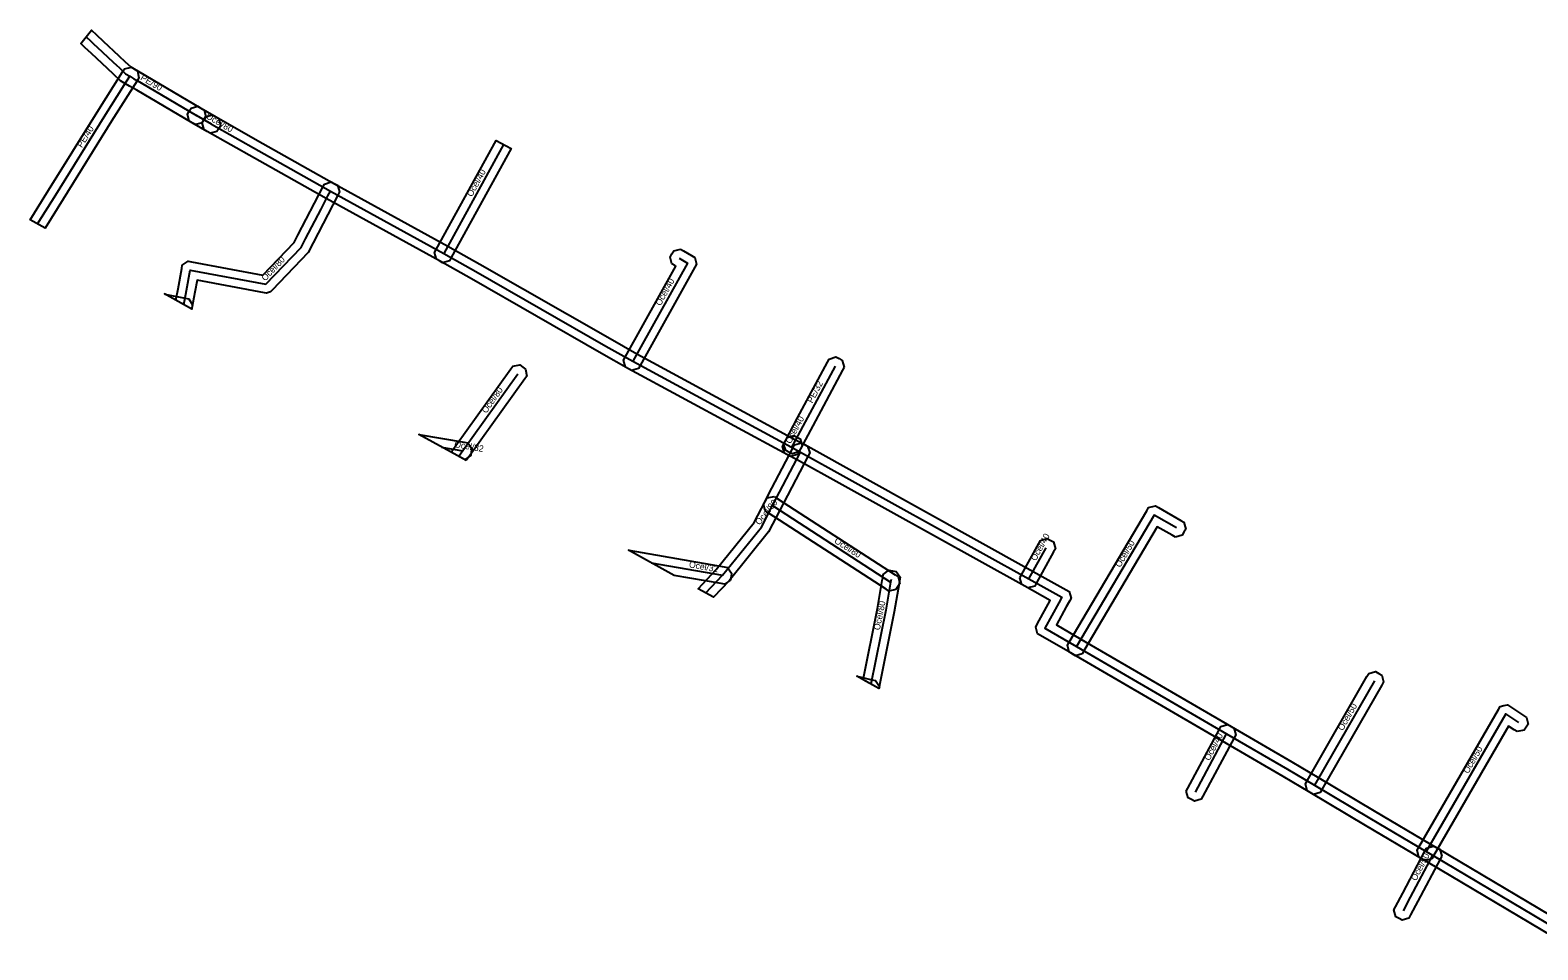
# Model space of a CAD drawing. Extents: x -749340 to -748632, y -965391 to -964902.
# Drawn here: x -749339.6 to -749163.1, y -965009.4 to -964901.7 of the extents above; entities that cross this region are included whole.
import ezdxf

# ---------------------------------------------------------------- set-up
doc = ezdxf.new("R2010")
doc.units = 0
for name, color, linetype in [('1', 7, 'Continuous'), ('14', 7, 'Continuous'), ('18', 7, 'Continuous'), ('20', 7, 'Continuous')]:
    doc.layers.add(name, color=color, linetype=linetype)

msp = doc.modelspace()

# ---------------------------------------------------------------- linework, layer by layer
at = {"layer": '1'}
for points in [[(-749333.19, -964903.71), (-749333.68, -964903.25), (-749332.42, -964901.69), (-749331.82, -964902.25), (-749331.06, -964902.97), (-749329.2, -964904.71), (-749328.47, -964905.4), (-749327.82, -964906), (-749327.43, -964906.23), (-749326.95, -964906.51), (-749326.11, -964907.01), (-749319.61, -964910.82), (-749319.25, -964911.03), (-749319.04, -964911.83), (-749319.25, -964912.19), (-749319.46, -964912.54), (-749320.26, -964912.75), (-749320.62, -964912.54), (-749327.12, -964908.73), (-749327.96, -964908.24), (-749328.44, -964907.96), (-749329.02, -964907.62), (-749329.83, -964906.85), (-749330.56, -964906.17), (-749332.42, -964904.43)], [(-749335.75, -964921.49), (-749337.85, -964924.86), (-749339.6, -964923.89), (-749337.45, -964920.43), (-749331.77, -964911.3), (-749328.78, -964906.56), (-749328.56, -964906.21), (-749327.75, -964906.03), (-749327.4, -964906.25), (-749327.05, -964906.47), (-749326.87, -964907.28), (-749327.09, -964907.63), (-749330.07, -964912.36)], [(-749318.54, -964913.76), (-749318.9, -964913.55), (-749320.62, -964912.54), (-749320.98, -964912.33), (-749321.19, -964911.53), (-749320.98, -964911.17), (-749320.77, -964910.82), (-749319.97, -964910.61), (-749319.61, -964910.82), (-749317.88, -964911.83), (-749317.53, -964912.04), (-749317.32, -964912.84), (-749317.53, -964913.2), (-749317.74, -964913.55)], [(-749292.07, -964927.36), (-749285.07, -964914.63), (-749283.29, -964915.56), (-749290.32, -964928.33), (-749290.52, -964928.69), (-749291.32, -964928.92), (-749291.68, -964928.72), (-749292.04, -964928.52), (-749292.27, -964927.73)], [(-749320.66, -964934.24), (-749320.68, -964934.35), (-749322.53, -964933.33), (-749322.29, -964932), (-749321.86, -964929.62), (-749321.79, -964929.21), (-749321.45, -964928.97), (-749321.11, -964928.73), (-749320.7, -964928.81), (-749312.35, -964930.37), (-749308.71, -964926.54), (-749308.26, -964925.68), (-749305.35, -964920.08), (-749305.16, -964919.71), (-749304.36, -964919.46), (-749304, -964919.66), (-749303.63, -964919.85), (-749303.38, -964920.64), (-749303.57, -964921.01), (-749306.49, -964926.6), (-749307.07, -964927.72), (-749311.27, -964932.14), (-749311.45, -964932.33), (-749311.93, -964932.48), (-749312.18, -964932.44), (-749320.07, -964930.96), (-749320.32, -964932.36)], [(-749263.48, -964927.33), (-749263.12, -964927.54), (-749262.18, -964928.09), (-749261.82, -964928.3), (-749261.61, -964929.09), (-749261.81, -964929.44), (-749268.21, -964940.95), (-749268.41, -964941.32), (-749269.21, -964941.54), (-749269.57, -964941.34), (-749269.93, -964941.14), (-749270.16, -964940.34), (-749269.96, -964939.98), (-749264.03, -964929.33), (-749264.13, -964929.27), (-749264.48, -964929.06), (-749264.7, -964928.26), (-749264.49, -964927.9), (-749264.28, -964927.55)], [(-749320.67, -964934.26), (-749320.68, -964934.35), (-749323.87, -964932.58), (-749323.82, -964932.59), (-749321.45, -964933.08), (-749321.04, -964933.17), (-749320.58, -964933.86)], [(-749288.56, -964952.1), (-749290.33, -964951.13), (-749289.77, -964950.35), (-749283.34, -964941.37), (-749283.1, -964941.04), (-749282.28, -964940.9), (-749281.95, -964941.14), (-749281.61, -964941.38), (-749281.47, -964942.2), (-749281.71, -964942.54), (-749288.15, -964951.52)], [(-749244.33, -964941.15), (-749244.52, -964941.51), (-749248.01, -964948.03), (-749249.45, -964950.71), (-749249.64, -964951.08), (-749250.43, -964951.32), (-749250.8, -964951.12), (-749251.16, -964950.93), (-749251.41, -964950.14), (-749251.21, -964949.77), (-749249.77, -964947.09), (-749246.29, -964940.57), (-749246.09, -964940.21), (-749245.3, -964939.96), (-749244.93, -964940.16), (-749244.57, -964940.36)], [(-749288.72, -964951.99), (-749288.78, -964951.98), (-749294.09, -964949.05), (-749288.79, -964949.95), (-749288.38, -964950.02), (-749287.9, -964950.7), (-749287.97, -964951.1), (-749288.04, -964951.51)], [(-749249.25, -964950.35), (-749249.45, -964950.71), (-749249.6, -964951), (-749249.8, -964951.37), (-749250.59, -964951.61), (-749250.95, -964951.41), (-749251.32, -964951.22), (-749251.56, -964950.43), (-749251.36, -964950.06), (-749251.21, -964949.77), (-749251.01, -964949.41), (-749250.22, -964949.17), (-749249.86, -964949.36), (-749249.49, -964949.56)], [(-749257.8, -964966.18), (-749259.62, -964968.1), (-749261.42, -964967.1), (-749259.31, -964964.86), (-749254.86, -964959.35), (-749253.59, -964956.91), (-749253.21, -964956.15), (-749250.32, -964950.64), (-749250.13, -964950.27), (-749249.34, -964950.02), (-749248.97, -964950.21), (-749248.6, -964950.41), (-749248.36, -964951.2), (-749248.55, -964951.56), (-749251.43, -964957.07), (-749251.81, -964957.82), (-749253.18, -964960.45)], [(-749252.51, -964956.3), (-749252.16, -964956.52), (-749238.34, -964965.48), (-749237.99, -964965.7), (-749237.82, -964966.51), (-749238.05, -964966.86), (-749238.27, -964967.21), (-749239.08, -964967.38), (-749239.43, -964967.15), (-749253.24, -964958.2), (-749253.59, -964957.98), (-749253.77, -964957.17), (-749253.54, -964956.82), (-749253.32, -964956.47)], [(-749205.56, -964961.06), (-749205.92, -964960.85), (-749207.68, -964959.84), (-749216.26, -964974.39), (-749216.47, -964974.75), (-749217.27, -964974.96), (-749217.63, -964974.75), (-749217.99, -964974.54), (-749218.19, -964973.73), (-749217.98, -964973.38), (-749208.91, -964957.97), (-749208.7, -964957.61), (-749207.9, -964957.4), (-749207.54, -964957.61), (-749204.93, -964959.12), (-749204.57, -964959.32), (-749204.35, -964960.12), (-749204.56, -964960.48), (-749204.76, -964960.84)], [(-749223.78, -964965.83), (-749223.58, -964965.46), (-749221.56, -964961.82), (-749221.36, -964961.45), (-749220.57, -964961.22), (-749220.2, -964961.42), (-749219.84, -964961.62), (-749219.61, -964962.42), (-749219.81, -964962.78), (-749221.83, -964966.43), (-749222.03, -964966.8), (-749222.83, -964967.02), (-749223.19, -964966.82), (-749223.55, -964966.62)], [(-749258.72, -964966.51), (-749264.23, -964965.55), (-749269.57, -964962.6), (-749269.53, -964962.61), (-749258.38, -964964.54), (-749257.97, -964964.61), (-749257.5, -964965.28), (-749257.57, -964965.69), (-749257.64, -964966.1), (-749258.32, -964966.58)], [(-749240.27, -964978.8), (-749242.11, -964977.78), (-749240.42, -964969.43), (-749239.87, -964966.15), (-749239.82, -964965.84), (-749239.75, -964965.44), (-749239.08, -964964.95), (-749238.67, -964965.02), (-749238.26, -964965.09), (-749237.78, -964965.76), (-749237.85, -964966.17), (-749237.9, -964966.48), (-749238.46, -964969.8)], [(-749240.21, -964978.54), (-749240.27, -964978.8), (-749242.86, -964977.36), (-749242.5, -964977.44), (-749241.07, -964977.76), (-749240.66, -964977.85)], [(-749181.2, -964978.03), (-749181.4, -964978.39), (-749188.41, -964990.61), (-749188.61, -964990.97), (-749189.41, -964991.19), (-749189.77, -964990.98), (-749190.13, -964990.78), (-749190.35, -964989.97), (-749190.14, -964989.62), (-749183.14, -964977.4), (-749182.93, -964977.04), (-749182.13, -964976.82), (-749181.77, -964977.02), (-749181.41, -964977.23)], [(-749165.56, -964983.84), (-749165.91, -964983.62), (-749166.56, -964983.19), (-749175.34, -964998.37), (-749175.55, -964998.73), (-749176.35, -964998.95), (-749176.71, -964998.74), (-749177.07, -964998.53), (-749177.28, -964997.73), (-749177.07, -964997.37), (-749167.76, -964981.27), (-749167.55, -964980.9), (-749167.13, -964980.8), (-749166.71, -964980.7), (-749166.35, -964980.93), (-749164.81, -964981.95), (-749164.46, -964982.17), (-749164.29, -964982.98), (-749164.52, -964983.33), (-749164.75, -964983.68)], [(-749204.29, -964990.81), (-749204.09, -964990.45), (-749200.44, -964983.62), (-749200.24, -964983.26), (-749199.45, -964983.02), (-749199.08, -964983.21), (-749198.72, -964983.41), (-749198.48, -964984.2), (-749198.68, -964984.57), (-749202.33, -964991.39), (-749202.53, -964991.76), (-749203.32, -964992), (-749203.68, -964991.8), (-749204.05, -964991.61)], [(-749174.39, -964998.42), (-749174.58, -964998.78), (-749177.19, -965003.7), (-749178.04, -965005.31), (-749178.23, -965005.67), (-749179.03, -965005.92), (-749179.39, -965005.72), (-749179.76, -965005.53), (-749180, -965004.73), (-749179.81, -965004.37), (-749178.96, -965002.76), (-749176.35, -964997.85), (-749176.16, -964997.48), (-749175.36, -964997.24), (-749175, -964997.43), (-749174.63, -964997.62)]]:
    msp.add_lwpolyline(points, close=True, dxfattribs=at)
msp.add_lwpolyline([(-749158.76, -965009.4), (-749175.98, -964999.17), (-749176.72, -964998.73), (-749183.31, -964994.82), (-749189.78, -964990.97), (-749192.94, -964989.1), (-749200.06, -964984.96), (-749217.62, -964974.75), (-749221.34, -964972.59), (-749221.7, -964972.38), (-749221.91, -964971.6), (-749221.72, -964971.24), (-749220.2, -964968.49), (-749223.19, -964966.82), (-749249.92, -964951.98), (-749250.96, -964951.41), (-749269.57, -964941.34), (-749272.72, -964939.56), (-749287.95, -964930.83), (-749291.68, -964928.72), (-749304.95, -964921.42), (-749313.33, -964916.69), (-749318.88, -964913.56), (-749319.24, -964913.36), (-749319.46, -964912.56), (-749319.26, -964912.2), (-749319.06, -964911.84), (-749318.26, -964911.62), (-749317.9, -964911.82), (-749312.35, -964914.95), (-749303.97, -964919.67), (-749290.71, -964926.97), (-749286.96, -964929.09), (-749271.73, -964937.82), (-749268.6, -964939.59), (-749250.01, -964949.65), (-749248.95, -964950.22), (-749222.22, -964965.08), (-749218.36, -964967.22), (-749217.99, -964967.42), (-749217.77, -964968.22), (-749217.97, -964968.58), (-749218.33, -964969.24), (-749219.49, -964971.35), (-749216.62, -964973.02), (-749199.05, -964983.23), (-749191.92, -964987.38), (-749188.76, -964989.25), (-749182.29, -964993.1), (-749175.7, -964997.01), (-749174.95, -964997.45), (-749157.74, -965007.68)], dxfattribs=at)
at = {"layer": '14'}
for points in [[(-749333.05, -964902.47), (-749332.51, -964902.98), (-749332.13, -964903.33), (-749331.74, -964903.7), (-749329.88, -964905.44), (-749329.51, -964905.79), (-749329.15, -964906.12), (-749328.42, -964906.81), (-749327.94, -964907.09), (-749327.45, -964907.38), (-749327.07, -964907.6), (-749326.62, -964907.87), (-749320.11, -964911.68)], [(-749338.72, -964924.37), (-749336.6, -964920.96), (-749330.92, -964911.83), (-749328.54, -964908.05), (-749327.94, -964907.09)], [(-749318.39, -964912.69), (-749320.11, -964911.68)]]:
    msp.add_lwpolyline(points, dxfattribs=at)
at = {"layer": '18'}
for points in [[(-749318.39, -964912.69), (-749312.84, -964915.82), (-749304.46, -964920.54), (-749291.2, -964927.84), (-749287.45, -964929.96), (-749272.23, -964938.69), (-749269.08, -964940.47), (-749250.48, -964950.53), (-749249.44, -964951.1), (-749222.71, -964965.95), (-749218.84, -964968.1), (-749219.2, -964968.75), (-749220.84, -964971.72), (-749217.12, -964973.88), (-749199.56, -964984.09), (-749192.43, -964988.24), (-749189.27, -964990.11), (-749182.8, -964993.96), (-749176.21, -964997.87), (-749175.47, -964998.31), (-749158.25, -965008.54)], [(-749284.18, -964915.09), (-749291.2, -964927.84)], [(-749321.6, -964933.84), (-749321.3, -964932.18), (-749320.88, -964929.79), (-749312, -964931.45), (-749307.89, -964927.13), (-749307.37, -964926.14), (-749305.55, -964922.64), (-749304.74, -964921.08), (-749304.46, -964920.54)], [(-749263.62, -964928.41), (-749262.68, -964928.96), (-749269.08, -964940.47)], [(-749245.4, -964941.04), (-749248.89, -964947.56), (-749250.33, -964950.24)], [(-749282.53, -964941.96), (-749288.96, -964950.94), (-749289.44, -964951.61)], [(-749291.44, -964950.51), (-749288.96, -964950.94)], [(-749260.52, -964967.6), (-749258.55, -964965.52), (-749254.02, -964959.9), (-749252.7, -964957.36), (-749252.32, -964956.61), (-749249.84, -964951.87), (-749249.44, -964951.1)], [(-749250.33, -964950.24), (-749250.48, -964950.53)], [(-749252.7, -964957.36), (-749238.89, -964966.32)], [(-749205.42, -964959.98), (-749208.04, -964958.48), (-749217.12, -964973.88)], [(-749222.71, -964965.95), (-749220.69, -964962.3)], [(-749266.9, -964964.08), (-749258.55, -964965.52)], [(-749238.84, -964966.01), (-749238.89, -964966.32), (-749239.44, -964969.61), (-749241.19, -964978.29)], [(-749182.27, -964977.89), (-749187.92, -964987.75), (-749189.27, -964990.11)], [(-749165.36, -964982.78), (-749166.9, -964981.77), (-749174.76, -964995.37), (-749176.21, -964997.87)], [(-749203.21, -964990.92), (-749199.56, -964984.09)], [(-749175.47, -964998.31), (-749178.07, -965003.23), (-749178.92, -965004.84)]]:
    msp.add_lwpolyline(points, dxfattribs=at)

# ---------------------------------------------------------------- texts
at = {"layer": '20'}
for s, rotation, p in [('PE/90', 329.5066, (-749326.76, -964907.46)), ('Ocel/80', 329.626, (-749319.1, -964911.96)), ('PE/40', 58.1132, (-749333.54, -964915.52)), ('Ocel/40', 61.1817, (-749287.89, -964921.27)), ('Ocel/80', 46.4472, (-749312.08, -964931.13)), ('Ocel/40', 60.9112, (-749265.82, -964934.04)), ('PE/32', 61.8441, (-749248.06, -964945.44)), ('Ocel/80', 54.396, (-749286.22, -964946.63)), ('Ocel/40', 61.8763, (-749250.6, -964950.19)), ('Ocel/32', 350.3126, (-749290, -964950.52)), ('Ocel/80', 51.1135, (-749254.24, -964959.72)), ('Ocel/80', 327.0552, (-749245.55, -964961.67)), ('Ocel/40', 61.0628, (-749221.9, -964963.92)), ('Ocel/50', 59.4917, (-749212.02, -964964.68)), ('Ocel/32', 350.1895, (-749262.53, -964964.6)), ('Ocel/80', 78.5995, (-749240.16, -964972.01)), ('Ocel/50', 60.1832, (-749185.97, -964983.8)), ('Ocel/40', 61.8361, (-749201.58, -964987.31)), ('Ocel/50', 59.9706, (-749171.29, -964988.82)), ('Ocel/50', 62.0717, (-749177.39, -965001.38))]:
    msp.add_text(s, height=0.75, rotation=rotation, dxfattribs=at).set_placement(p)

doc.saveas('drawing.dxf')
